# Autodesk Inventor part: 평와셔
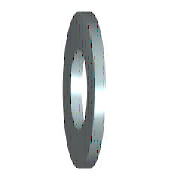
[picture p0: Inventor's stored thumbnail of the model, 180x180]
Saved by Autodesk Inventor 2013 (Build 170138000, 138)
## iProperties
IsCustomPart: 1
Created: 2012-02
Part Number: 평와셔
Material: 강철
Description: 평면 와셔 - 초대형 시리즈 - 제품 등급 C
Document SubType Name: Modeling
Standard: ISO 7094
Designer: mduedu
Standard Revision: Second edition 2000-06-01
Standards Organization: ISO
Language: ko-KR
Size Designation: ST 5 - 100 HV
Categories: <MemberInstance><Categories><Category DisplayName="조임쇠" InternalName="e4da775c-781d-43d5-af7c-5136215cf5a6" Mnemonic="FSTN"><Category DisplayName="와셔" InternalN
Density: 7.85 g/cm^3
Mass: 3.62216 g
Surface Area: 6.09076 cm^2
Volume: 0.461421 cm^3
Author: mduedu
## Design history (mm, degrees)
sketch "스케치"
  geometry: C1 r 9 at (0, 0); C2 r 2.75 at (0, 0); 1 further point
  constraints: 2 centre point, 2 coincident
  dimensions: "d0" = 5.5 diameter of C2 (= SD1); "d1" = 18 diameter of C1 (= SD2)
extrude "본체" new body sketch "스케치" distance "d2" = 2 (= SD); taper "d3" = 0 deg
workaxis "Work Axis1"
workplane "Work Plane1"
body "Solid1"
other parameters: "SD1" = 5.5 [user parameter; used in 1 equation term], "SD2" = 18 [user parameter; used in 1 equation term], "SD" = 2 [user parameter; used in 1 equation term], "d4" = 0, "d5" = 0, "d6" = 0, "d7" = 0, "NND" = 5 [user parameter]
